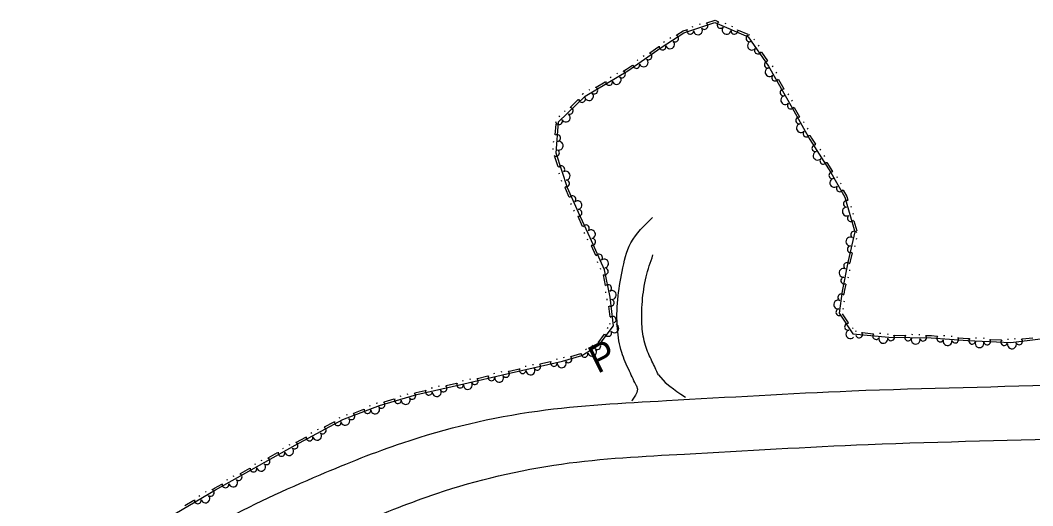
# Model space of a CAD drawing. Extents: x 2030130 to 2036320, y 723205 to 762423.
# Drawn here: x 2034092 to 2034480.3, y 761016.9 to 761203.3 of the extents above; entities that cross this region are included whole.
import ezdxf

# ---------------------------------------------------------------- set-up
doc = ezdxf.new("R2010")
doc.units = 0
for name, color, linetype in [('Draft_Station Labels Major', 7, 'Continuous'), ('Draft_Station Tics Major', 7, 'Continuous'), ('Prop Horizontal Alignment Ramp', 7, 'Continuous')]:
    doc.layers.add(name, color=color, linetype=linetype)

msp = doc.modelspace()

# ---------------------------------------------------------------- linework, layer by layer
at = {"layer": 'Draft_Station Labels Major'}
for points in [[(2034336.79, 761067.2), (2034339.37, 761064.27), (2034341.21, 761062.76), (2034342.51, 761061.76), (2034343.84, 761060.72), (2034345.32, 761059.69), (2034347.12, 761058.55)], [(2034328.39, 761062.89), (2034328.69, 761061.64), (2034328.44, 761060.43), (2034327.97, 761059.35), (2034327.45, 761058.52), (2034326.77, 761057.44), (2034326.54, 761057.07)]]:
    msp.add_lwpolyline(points, dxfattribs=at)
for points in [[(2034328.47, 761062.72), (2034325.66, 761068.53), (2034322.69, 761075.78), (2034321.08, 761084.75), (2034321.19, 761096.11), (2034322.86, 761106.84), (2034326.23, 761117.82), (2034334.55, 761127.48)], [(2034336.79, 761067.2), (2034334.28, 761072.38), (2034331.8, 761078.44), (2034330.52, 761085.55), (2034330.61, 761095.34), (2034332.08, 761104.72), (2034334.67, 761113.16)], [(2034092.04, 760960.15), (2034128.02, 760985.27), (2034167.72, 761010.14), (2034207.02, 761028.78), (2034238.75, 761041.08), (2034290.36, 761053.26), (2034339.84, 761057.27), (2034410.92, 761061), (2034496.35, 761063.49), (2034597.04, 761068.5), (2034676.22, 761073.92), (2034760.74, 761078.95), (2034860.07, 761085.08), (2034928.36, 761090.57)], [(2034112.77, 760944.64), (2034147.71, 760969.04), (2034185.56, 760992.74), (2034222.61, 761010.31), (2034251.75, 761021.61), (2034299.66, 761032.92), (2034346.78, 761036.74), (2034417.19, 761040.43), (2034502.59, 761042.92), (2034603.78, 761047.95), (2034683.1, 761053.38), (2034767.53, 761058.4), (2034867.13, 761064.56), (2034935.91, 761070.08)]]:
    msp.add_spline(points, degree=3, dxfattribs=at)
at = {"layer": 'Draft_Station Tics Major'}
for points in [[(2034146.32, 761010.81), (2034166.94, 761022.97), (2034197.43, 761040.12), (2034215.78, 761050.01), (2034229.84, 761055.38), (2034244.1, 761059.58), (2034260.48, 761063.36), (2034280.33, 761067.95), (2034300.03, 761072.46), (2034307.36, 761074.54), (2034314.06, 761078.62), (2034319.52, 761085.92), (2034318.23, 761096.97), (2034316.07, 761107.5), (2034310.65, 761119.75), (2034306.1, 761129.47), (2034301.91, 761138.93), (2034297.5, 761152.2), (2034298.45, 761164.3), (2034308.67, 761174.17), (2034325.02, 761183.78), (2034337.89, 761192.83), (2034346.58, 761198.42), (2034358.44, 761202.38), (2034371.25, 761196.9), (2034379.05, 761185.68), (2034388.02, 761169.61), (2034394.82, 761157.51), (2034402.86, 761144.83), (2034408.28, 761135.34), (2034412.07, 761122.01), (2034409.53, 761110.97), (2034407.22, 761099.23), (2034406.11, 761090.77), (2034411.27, 761082.87), (2034425.2, 761081.55), (2034441.4, 761081.39), (2034455.43, 761080.3), (2034471.87, 761079.61), (2034483.29, 761080.92)], [(2034352.5, 761201.69), (2034352.89, 761201.82)], [(2034355.35, 761202.21), (2034358.48, 761203.25), (2034359.79, 761202.69)], [(2034362.21, 761202.1), (2034362.59, 761201.94)], [(2034343.8, 761197.6), (2034346.22, 761199.16), (2034347.57, 761199.61)], [(2034349.78, 761200.78), (2034350.16, 761200.91)], [(2034364.85, 761200.97), (2034365.23, 761200.81)], [(2034367.33, 761199.47), (2034371.1, 761197.85)], [(2034338.74, 761194.84), (2034339.09, 761195.06)], [(2034341.16, 761196.39), (2034341.5, 761196.62)], [(2034373.37, 761196), (2034373.61, 761195.67)], [(2034375.01, 761193.65), (2034375.25, 761193.31)], [(2034330.95, 761189.45), (2034331.28, 761189.69)], [(2034333.53, 761190.77), (2034336.89, 761193.12)], [(2034376.32, 761191.05), (2034378.66, 761187.69)], [(2034323.46, 761183.82), (2034324.58, 761184.47), (2034326.82, 761186.05)], [(2034328.6, 761187.8), (2034328.93, 761188.03)], [(2034320.78, 761182.71), (2034321.14, 761182.92)], [(2034380.41, 761185.77), (2034380.61, 761185.41)], [(2034381.81, 761183.26), (2034382.01, 761182.91)], [(2034312.86, 761177.58), (2034316.39, 761179.66)], [(2034318.31, 761181.26), (2034318.66, 761181.47)], [(2034382.85, 761180.55), (2034384.85, 761176.97)], [(2034307.53, 761174.77), (2034307.9, 761175.13), (2034308, 761175.19)], [(2034310.18, 761176.48), (2034310.53, 761176.69)], [(2034386.41, 761175.02), (2034386.61, 761174.67)], [(2034303.09, 761169.92), (2034306.04, 761172.77)], [(2034387.81, 761172.52), (2034388.01, 761172.16)], [(2034298.68, 761166.23), (2034298.97, 761166.51)], [(2034300.74, 761168.22), (2034301.03, 761168.51)], [(2034388.85, 761169.82), (2034390.86, 761166.24)], [(2034297.23, 761159.32), (2034297.55, 761163.41)], [(2034392.42, 761164.29), (2034392.62, 761163.94)], [(2034393.83, 761161.79), (2034394.03, 761161.43)], [(2034394.88, 761159.09), (2034395.52, 761157.93), (2034396.99, 761155.63)], [(2034296.6, 761156.49), (2034296.63, 761156.9)], [(2034296.38, 761153.63), (2034296.41, 761154.04)], [(2034298.37, 761146.98), (2034297.07, 761150.87)], [(2034398.65, 761153.77), (2034398.87, 761153.42)], [(2034400.19, 761151.34), (2034400.41, 761151)], [(2034401.38, 761148.7), (2034403.57, 761145.25), (2034403.6, 761145.2)], [(2034298.89, 761144.13), (2034298.76, 761144.52)], [(2034405.17, 761143.27), (2034405.38, 761142.91)], [(2034299.79, 761141.41), (2034299.66, 761141.79)], [(2034302.6, 761135.36), (2034301.15, 761138.63), (2034300.96, 761139.2)], [(2034406.6, 761140.78), (2034406.8, 761140.42)], [(2034407.66, 761138.08), (2034409.05, 761135.66), (2034409.46, 761134.2)], [(2034303.38, 761132.57), (2034303.22, 761132.94)], [(2034410.53, 761131.95), (2034410.64, 761131.56)], [(2034304.55, 761129.94), (2034304.38, 761130.32)], [(2034307.69, 761124.14), (2034305.95, 761127.86)], [(2034411.31, 761129.19), (2034411.42, 761128.79)], [(2034411.7, 761126.31), (2034412.82, 761122.37)], [(2034308.54, 761121.37), (2034308.36, 761121.74)], [(2034309.73, 761118.79), (2034309.57, 761119.16)], [(2034312.76, 761112.95), (2034311.1, 761116.7)], [(2034412.11, 761116.68), (2034412.01, 761116.28)], [(2034412.75, 761119.47), (2034412.66, 761119.07)], [(2034411.06, 761113.97), (2034410.33, 761110.8), (2034410.17, 761109.99)], [(2034313.55, 761110.16), (2034313.38, 761110.54)], [(2034314.71, 761107.53), (2034314.55, 761107.91)], [(2034316.47, 761101.48), (2034315.65, 761105.5)], [(2034409.55, 761104.69), (2034409.47, 761104.28)], [(2034410.1, 761107.5), (2034410.02, 761107.1)], [(2034408.59, 761101.95), (2034408.03, 761099.09), (2034407.88, 761097.96)], [(2034316.65, 761098.59), (2034316.56, 761098.99)], [(2034317.12, 761095.86), (2034317.08, 761096.27)], [(2034318.29, 761089.4), (2034317.82, 761093.47)], [(2034407.59, 761092.62), (2034407.54, 761092.22)], [(2034407.96, 761095.47), (2034407.91, 761095.06)], [(2034407.25, 761090.51), (2034409.5, 761087.08)], [(2034317.25, 761084.94), (2034317.49, 761085.27)], [(2034318.22, 761086.5), (2034318.17, 761086.9)], [(2034411.19, 761085.24), (2034411.41, 761084.9)], [(2034313.65, 761079.44), (2034316.1, 761082.72)], [(2034412.21, 761084.01), (2034412.62, 761083.97)], [(2034415.03, 761083.34), (2034419.12, 761082.95)], [(2034421.6, 761083.13), (2034422.01, 761083.09)], [(2034424.46, 761082.86), (2034424.87, 761082.82)], [(2034427.22, 761082.35), (2034431.32, 761082.31)], [(2034433.79, 761082.7), (2034434.2, 761082.69)], [(2034436.66, 761082.67), (2034437.07, 761082.66)], [(2034439.52, 761082.23), (2034441.44, 761082.21), (2034443.67, 761082.04)], [(2034446.16, 761082.25), (2034446.57, 761082.22)], [(2034449.02, 761082.03), (2034449.43, 761082)], [(2034451.85, 761081.4), (2034455.48, 761081.12), (2034455.91, 761081.1)], [(2034458.39, 761081.41), (2034458.8, 761081.39)], [(2034461.26, 761081.29), (2034461.67, 761081.27)], [(2034473.35, 761081.02), (2034473.75, 761081.07)], [(2034476.25, 761080.94), (2034480.32, 761081.41)], [(2034308.86, 761076.9), (2034309.21, 761077.11)], [(2034311.31, 761078.39), (2034311.66, 761078.6)], [(2034464.11, 761080.76), (2034468.2, 761080.59)], [(2034470.68, 761080.9), (2034471.09, 761080.88)], [(2034297.64, 761073.18), (2034298.04, 761073.27)], [(2034300.36, 761073.84), (2034300.76, 761073.95)], [(2034303.24, 761074.23), (2034307.03, 761075.3)], [(2034279.34, 761068.57), (2034280.15, 761068.75), (2034283.34, 761069.48)], [(2034285.64, 761070.43), (2034286.04, 761070.52)], [(2034288.44, 761071.07), (2034288.84, 761071.17)], [(2034291.33, 761071.32), (2034295.33, 761072.23)], [(2034264.46, 761065.54), (2034264.86, 761065.64)], [(2034267.35, 761065.79), (2034271.35, 761066.72)], [(2034273.65, 761067.67), (2034274.05, 761067.76)], [(2034276.45, 761068.32), (2034276.85, 761068.41)], [(2034249.68, 761062.13), (2034250.08, 761062.22)], [(2034252.48, 761062.78), (2034252.87, 761062.87)], [(2034255.36, 761063.02), (2034259.36, 761063.94)], [(2034261.66, 761064.9), (2034262.06, 761064.99)], [(2034231.54, 761056.73), (2034235.47, 761057.89)], [(2034237.71, 761058.98), (2034238.11, 761059.1)], [(2034240.47, 761059.79), (2034240.86, 761059.91)], [(2034243.34, 761060.21), (2034243.89, 761060.37), (2034247.37, 761061.18)], [(2034219.93, 761052.47), (2034223.76, 761053.93)], [(2034225.92, 761055.2), (2034226.3, 761055.34)], [(2034228.59, 761056.22), (2034228.98, 761056.36)], [(2034214.33, 761050.63), (2034214.69, 761050.82)], [(2034217.1, 761051.83), (2034217.48, 761051.98)], [(2034206.03, 761046.15), (2034206.39, 761046.34)], [(2034208.75, 761047.15), (2034212.36, 761049.1)], [(2034197.92, 761041.31), (2034201.53, 761043.26)], [(2034203.5, 761044.79), (2034203.86, 761044.98)], [(2034192.69, 761038.86), (2034193.05, 761039.06)], [(2034195.19, 761040.27), (2034195.55, 761040.47)], [(2034184.47, 761034.24), (2034184.83, 761034.44)], [(2034187.17, 761035.29), (2034190.75, 761037.3)], [(2034176.45, 761029.26), (2034180.02, 761031.27)], [(2034181.97, 761032.83), (2034182.32, 761033.04)], [(2034171.24, 761026.8), (2034171.6, 761027.01)], [(2034173.75, 761028.21), (2034174.1, 761028.41)], [(2034165.72, 761023.2), (2034166.53, 761023.68), (2034169.3, 761025.24)], [(2034155.12, 761016.95), (2034158.65, 761019.04)], [(2034160.57, 761020.64), (2034160.92, 761020.85)], [(2034163.04, 761022.1), (2034163.39, 761022.31)]]:
    msp.add_lwpolyline(points, dxfattribs=at)
for centre, radius, start, end in [((2034354.44, 761201.04), 1.3, 216.8842, 57.6807), ((2034360.6, 761201.45), 1.3, 117.608, 318.4045), ((2034343.2, 761196.25), 1.3, 231.2016, 71.9982), ((2034349, 761199.23), 1.3, 159.2177, 0.0143), ((2034351.98, 761199.36), 1.69, 184.413, 32.4854), ((2034362.92, 761199.57), 1.69, 142.8032, 350.8757), ((2034365.88, 761199.2), 1.3, 175.2744, 16.071), ((2034371.66, 761196.31), 1.3, 85.5835, 286.3801), ((2034341.23, 761194), 1.69, 198.7304, 46.8029), ((2034372.63, 761193.48), 1.69, 110.7788, 318.8513), ((2034333, 761189.39), 1.3, 233.5464, 74.343), ((2034338.38, 761193.14), 1.3, 173.5351, 14.3317), ((2034374.94, 761191.6), 1.3, 143.25, 344.0466), ((2034328.3, 761186.08), 1.3, 175.88, 16.6765), ((2034331.12, 761187.06), 1.69, 201.0752, 49.1477), ((2034378.69, 761186.21), 1.3, 85.5835, 286.3801), ((2034322.82, 761182.48), 1.3, 228.8888, 69.6854), ((2034379.42, 761183.34), 1.69, 105.1382, 313.2107), ((2034381.54, 761181.23), 1.3, 137.6094, 338.4059), ((2034317.87, 761179.57), 1.3, 171.2223, 12.0189), ((2034320.76, 761180.32), 1.69, 196.4176, 44.4901), ((2034310.15, 761174.09), 1.69, 196.4176, 44.4901), ((2034312.21, 761176.25), 1.3, 228.8888, 69.6854), ((2034384.74, 761175.5), 1.3, 79.9429, 280.7395), ((2034385.42, 761172.59), 1.69, 105.1382, 313.2107), ((2034307.5, 761173.03), 1.3, 184.751, 25.5476), ((2034387.54, 761170.49), 1.3, 137.6094, 338.4059), ((2034301.28, 761165.89), 1.69, 209.9463, 58.0188), ((2034302.77, 761168.48), 1.3, 242.4175, 83.214), ((2034298.64, 761164.49), 1.3, 184.751, 25.5476), ((2034390.75, 761164.76), 1.3, 80.0866, 280.8831), ((2034391.44, 761161.86), 1.69, 105.2818, 313.3543), ((2034297.95, 761158.03), 1.3, 283.9469, 124.7434), ((2034393.56, 761159.76), 1.3, 137.753, 338.5496), ((2034298.55, 761155.1), 1.69, 251.4757, 99.5482), ((2034396.95, 761154.15), 1.3, 83.1492, 283.9458), ((2034297.51, 761152.31), 1.3, 226.2804, 67.077), ((2034397.8, 761151.28), 1.69, 108.3445, 316.417), ((2034299.53, 761146.08), 1.3, 306.8359, 147.6325), ((2034400.03, 761149.3), 1.3, 140.8157, 341.6123), ((2034301.22, 761143.61), 1.69, 274.3647, 122.4372), ((2034403.49, 761143.73), 1.3, 80.5134, 281.3099), ((2034301.35, 761140.63), 1.3, 249.1694, 89.966), ((2034404.21, 761140.83), 1.69, 105.7086, 313.7811), ((2034406.34, 761138.74), 1.3, 138.1798, 338.9764), ((2034303.84, 761134.57), 1.3, 312.3251, 153.1216), ((2034305.76, 761132.27), 1.69, 279.8539, 127.9264), ((2034409, 761129.81), 1.69, 91.8272, 299.8997), ((2034409.01, 761132.8), 1.3, 66.6319, 267.4285), ((2034306.17, 761129.32), 1.3, 255.8587, 96.6552), ((2034410.58, 761127.27), 1.3, 124.2984, 325.0949), ((2034308.96, 761123.38), 1.3, 313.5251, 154.3217), ((2034310.92, 761121.12), 1.69, 281.0539, 129.1264), ((2034410.38, 761118.34), 1.69, 62.9934, 271.0659), ((2034411.83, 761120.95), 1.3, 37.7981, 238.5947), ((2034311.36, 761118.16), 1.3, 254.6369, 95.4335), ((2034410.54, 761115.35), 1.3, 95.4646, 296.2611), ((2034314.01, 761112.16), 1.3, 312.3034, 153.1), ((2034315.92, 761109.87), 1.69, 279.8322, 127.9047), ((2034316.2, 761106.87), 1.3, 242.3613, 83.1579), ((2034409.13, 761108.95), 1.3, 39.6311, 240.4276), ((2034407.77, 761106.29), 1.69, 64.8264, 272.8988), ((2034408.02, 761103.31), 1.3, 97.2975, 298.0941), ((2034317.52, 761100.44), 1.3, 300.0278, 140.8244), ((2034318.9, 761097.79), 1.69, 267.5566, 115.6291), ((2034406.9, 761096.85), 1.3, 43.2936, 244.0902), ((2034318.49, 761094.79), 1.3, 237.4279, 78.2245), ((2034405.72, 761094.11), 1.69, 68.4889, 276.5614), ((2034319.25, 761088.27), 1.3, 295.0944, 135.891), ((2034406.16, 761091.16), 1.3, 100.9601, 301.7566), ((2034319.87, 761085.02), 1.69, 219.1402, 67.2127), ((2034409.48, 761085.6), 1.3, 83.927, 284.7235), ((2034317.5, 761083.22), 1.3, 193.945, 34.7415), ((2034410.36, 761082.75), 1.69, 109.1222, 317.1947), ((2034413.73, 761082.63), 1.3, 193.0553, 33.8519), ((2034420.26, 761082.02), 1.3, 135.3888, 336.1854), ((2034423.04, 761080.93), 1.69, 160.5841, 8.6566), ((2034425.98, 761081.55), 1.3, 197.855, 38.6516), ((2034432.54, 761081.48), 1.3, 140.1886, 340.9851), ((2034435.41, 761080.63), 1.69, 165.3838, 13.4563), ((2034438.29, 761081.42), 1.3, 197.855, 38.6516), ((2034444.84, 761081.12), 1.3, 136.3303, 337.1269), ((2034450.56, 761080.68), 1.3, 193.9968, 34.7934), ((2034457.11, 761080.23), 1.3, 138.3774, 339.174), ((2034311.33, 761076), 1.69, 197.3294, 45.4019), ((2034313.36, 761078.2), 1.3, 229.8006, 70.5972), ((2034447.64, 761080.08), 1.69, 161.5256, 9.5981), ((2034459.94, 761079.29), 1.69, 163.5727, 11.6452), ((2034462.84, 761079.99), 1.3, 196.0439, 36.8405), ((2034469.4, 761079.72), 1.3, 138.3774, 339.174), ((2034472.36, 761078.85), 1.69, 172.4895, 20.562), ((2034475.12, 761079.99), 1.3, 204.9607, 45.7572), ((2034302.28, 761073.1), 1.3, 214.2474, 55.044), ((2034308.45, 761075.21), 1.3, 172.1341, 12.9307), ((2034284.72, 761068.96), 1.3, 153.6679, 354.4645), ((2034287.7, 761068.8), 1.69, 178.8632, 26.9357), ((2034290.31, 761070.24), 1.3, 211.3344, 52.1309), ((2034296.71, 761071.71), 1.3, 153.6679, 354.4645), ((2034299.69, 761071.55), 1.69, 178.8632, 26.9357), ((2034266.34, 761064.72), 1.3, 211.4636, 52.2602), ((2034272.73, 761066.2), 1.3, 153.7972, 354.5937), ((2034275.71, 761066.04), 1.69, 178.9924, 27.0649), ((2034278.32, 761067.49), 1.3, 211.4636, 52.2602), ((2034254.35, 761061.95), 1.3, 211.4319, 52.2284), ((2034260.74, 761063.42), 1.3, 153.7972, 354.5937), ((2034263.72, 761063.27), 1.69, 178.9924, 27.0649), ((2034236.88, 761057.45), 1.3, 157.1934, 357.9899), ((2034239.87, 761057.48), 1.69, 182.3886, 30.4611), ((2034242.39, 761059.08), 1.3, 214.8598, 55.6564), ((2034248.75, 761060.65), 1.3, 153.7654, 354.562), ((2034251.74, 761060.5), 1.69, 178.9607, 27.0332), ((2034225.2, 761053.61), 1.3, 161.6518, 2.4484), ((2034228.18, 761053.86), 1.69, 186.8471, 34.9196), ((2034230.59, 761055.6), 1.3, 214.8598, 55.6564), ((2034216.68, 761049.48), 1.69, 186.8471, 34.9196), ((2034219.07, 761051.27), 1.3, 219.3183, 60.1149), ((2034208.05, 761045.85), 1.3, 226.7727, 67.5692), ((2034213.83, 761048.96), 1.3, 169.1062, 9.9028), ((2034203, 761043.12), 1.3, 169.1062, 9.9028), ((2034205.92, 761043.76), 1.69, 194.3015, 42.374), ((2034195.13, 761037.88), 1.69, 195.3105, 43.383), ((2034197.23, 761040), 1.3, 227.7817, 68.5783), ((2034186.5, 761033.97), 1.3, 227.7817, 68.5783), ((2034192.22, 761037.19), 1.3, 170.1153, 10.9118), ((2034181.5, 761031.16), 1.3, 170.1153, 10.9118), ((2034184.4, 761031.85), 1.69, 195.3105, 43.383), ((2034173.68, 761025.82), 1.69, 195.3105, 43.383), ((2034175.78, 761027.94), 1.3, 227.7817, 68.5783), ((2034165.08, 761021.87), 1.3, 228.9758, 69.7724), ((2034170.77, 761025.13), 1.3, 170.1153, 10.9118), ((2034160.13, 761018.96), 1.3, 171.3094, 12.1059), ((2034163.02, 761019.71), 1.69, 196.5046, 44.5771)]:
    msp.add_arc(centre, radius, start, end, dxfattribs=at)

# ---------------------------------------------------------------- texts
at = {"layer": 'Prop Horizontal Alignment Ramp'}
msp.add_text('P', height=10.66, rotation=26.3279, dxfattribs=at).set_placement((2034313.4, 761067.44))

doc.saveas('drawing.dxf')
